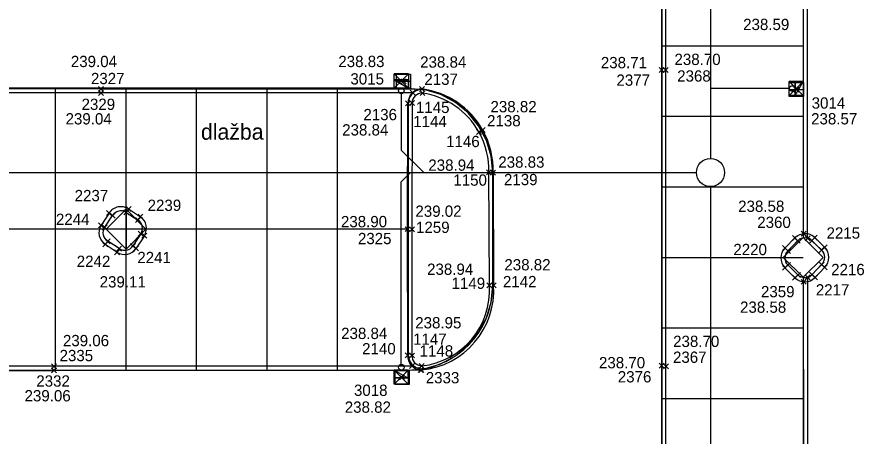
# Model space of a CAD drawing. Extents: x -264222 to -263676, y -1242344 to -1242060.
# Drawn here: x -264148.43 to -264118.41, y -1242246.81 to -1242231.96 of the extents above; entities that cross this region are included whole.
import ezdxf

# ---------------------------------------------------------------- set-up
doc = ezdxf.new("R2010")
doc.units = 0
for name, color, linetype in [('BODY_CISLO', 7, 'Continuous'), ('BODY_SYMBOL', 7, 'Continuous'), ('BODY_VYSKA', 7, 'Continuous'), ('BODY_VYSKY_UV', 7, 'Continuous'), ('KOORDINACNA_SITUACIA_DSP', 7, 'Continuous'), ('POPIS', 7, 'Continuous'), ('PROJEKT_DRS_OBRUBNIKY_KOMUNIKACIE', 7, 'Continuous'), ('PROJEKT_DRS_TDZ_VODOROVNE', 7, 'Continuous'), ('PROJEKT_DRS_UV_STAVBY', 7, 'Continuous'), ('SO_20-3_OBRUBNIKY_DOLNA_HRANA', 7, 'Continuous'), ('SO_20-3_OBRUBNIKY_HORNA_HRANA', 7, 'Continuous'), ('ULICNA_VPUST_POKLOP', 7, 'Continuous')]:
    doc.layers.add(name, color=color, linetype=linetype)

msp = doc.modelspace()

# ---------------------------------------------------------------- linework, layer by layer
at = {"layer": 'BODY_SYMBOL'}
for p, q in [((-264125.67, -1242233.932), (-264125.494, -1242233.756)), ((-264125.494, -1242233.932), (-264125.67, -1242233.756)), ((-264125.527, -1242233.933), (-264125.351, -1242233.757)), ((-264125.351, -1242233.933), (-264125.527, -1242233.757)), ((-264134.821, -1242234.328), (-264134.645, -1242234.152)), ((-264134.645, -1242234.328), (-264134.821, -1242234.152)), ((-264145.543, -1242234.743), (-264145.367, -1242234.567)), ((-264145.367, -1242234.743), (-264145.543, -1242234.567)), ((-264145.541, -1242234.6), (-264145.365, -1242234.424)), ((-264145.365, -1242234.6), (-264145.541, -1242234.424)), ((-264134.502, -1242234.739), (-264134.326, -1242234.563)), ((-264134.326, -1242234.739), (-264134.502, -1242234.563)), ((-264134.167, -1242234.605), (-264133.991, -1242234.429)), ((-264133.991, -1242234.605), (-264134.167, -1242234.429)), ((-264120.898, -1242234.625), (-264120.722, -1242234.449)), ((-264120.722, -1242234.625), (-264120.898, -1242234.449)), ((-264134.149, -1242234.752), (-264133.973, -1242234.576)), ((-264133.973, -1242234.752), (-264134.149, -1242234.576)), ((-264134.664, -1242235.109), (-264134.488, -1242234.933)), ((-264134.488, -1242235.109), (-264134.664, -1242234.933)), ((-264134.517, -1242235.105), (-264134.341, -1242234.929)), ((-264134.341, -1242235.105), (-264134.517, -1242234.929)), ((-264132.148, -1242236.128), (-264131.972, -1242235.952)), ((-264131.972, -1242236.128), (-264132.148, -1242235.952)), ((-264132.017, -1242236.054), (-264131.841, -1242235.878)), ((-264131.841, -1242236.054), (-264132.017, -1242235.878)), ((-264131.797, -1242237.561), (-264131.621, -1242237.385)), ((-264131.621, -1242237.561), (-264131.797, -1242237.385)), ((-264131.649, -1242237.572), (-264131.473, -1242237.396)), ((-264131.473, -1242237.572), (-264131.649, -1242237.396)), ((-264144.565, -1242238.856), (-264144.389, -1242238.68)), ((-264144.389, -1242238.856), (-264144.565, -1242238.68)), ((-264145.254, -1242239), (-264145.078, -1242238.824)), ((-264145.078, -1242239), (-264145.254, -1242238.824)), ((-264145.133, -1242239.089), (-264144.957, -1242238.913)), ((-264144.957, -1242239.089), (-264145.133, -1242238.913)), ((-264144.646, -1242238.975), (-264144.47, -1242238.799)), ((-264144.47, -1242238.975), (-264144.646, -1242238.799)), ((-264144.226, -1242239.248), (-264144.05, -1242239.072)), ((-264144.05, -1242239.248), (-264144.226, -1242239.072)), ((-264144.142, -1242239.129), (-264143.966, -1242238.953)), ((-264143.966, -1242239.129), (-264144.142, -1242238.953)), ((-264145.539, -1242239.434), (-264145.363, -1242239.258)), ((-264145.363, -1242239.434), (-264145.539, -1242239.258)), ((-264145.407, -1242239.506), (-264145.231, -1242239.33)), ((-264145.231, -1242239.506), (-264145.407, -1242239.33)), ((-264144.133, -1242239.733), (-264143.957, -1242239.557)), ((-264143.957, -1242239.733), (-264144.133, -1242239.557)), ((-264144.003, -1242239.802), (-264143.827, -1242239.626)), ((-264143.827, -1242239.802), (-264144.003, -1242239.626)), ((-264134.675, -1242239.571), (-264134.499, -1242239.395)), ((-264134.499, -1242239.571), (-264134.675, -1242239.395)), ((-264134.525, -1242239.573), (-264134.349, -1242239.397)), ((-264134.349, -1242239.573), (-264134.525, -1242239.397)), ((-264120.642, -1242239.734), (-264120.466, -1242239.558)), ((-264120.466, -1242239.734), (-264120.642, -1242239.558)), ((-264145.393, -1242240.113), (-264145.217, -1242239.937)), ((-264145.217, -1242240.113), (-264145.393, -1242239.937)), ((-264145.3, -1242239.997), (-264145.124, -1242239.821)), ((-264145.124, -1242239.997), (-264145.3, -1242239.821)), ((-264120.952, -1242239.881), (-264120.776, -1242239.705)), ((-264120.776, -1242239.881), (-264120.952, -1242239.705)), ((-264120.85, -1242239.985), (-264120.674, -1242239.809)), ((-264120.674, -1242239.985), (-264120.85, -1242239.809)), ((-264120.502, -1242239.891), (-264120.326, -1242239.715)), ((-264120.326, -1242239.891), (-264120.502, -1242239.715)), ((-264120.351, -1242239.976), (-264120.175, -1242239.8)), ((-264120.175, -1242239.976), (-264120.351, -1242239.8)), ((-264120.248, -1242239.871), (-264120.072, -1242239.695)), ((-264120.072, -1242239.871), (-264120.248, -1242239.695)), ((-264144.97, -1242240.393), (-264144.794, -1242240.217)), ((-264144.794, -1242240.393), (-264144.97, -1242240.217)), ((-264144.901, -1242240.259), (-264144.725, -1242240.083)), ((-264144.725, -1242240.259), (-264144.901, -1242240.083)), ((-264144.409, -1242240.165), (-264144.233, -1242239.989)), ((-264144.233, -1242240.165), (-264144.409, -1242239.989)), ((-264144.297, -1242240.248), (-264144.121, -1242240.072)), ((-264144.121, -1242240.248), (-264144.297, -1242240.072)), ((-264121.301, -1242240.234), (-264121.125, -1242240.058)), ((-264121.125, -1242240.234), (-264121.301, -1242240.058)), ((-264121.198, -1242240.342), (-264121.022, -1242240.166)), ((-264121.022, -1242240.342), (-264121.198, -1242240.166)), ((-264120.008, -1242240.31), (-264119.832, -1242240.134)), ((-264119.832, -1242240.31), (-264120.008, -1242240.134)), ((-264119.898, -1242240.211), (-264119.722, -1242240.035)), ((-264119.722, -1242240.211), (-264119.898, -1242240.035)), ((-264121.307, -1242240.941), (-264121.131, -1242240.765)), ((-264121.131, -1242240.941), (-264121.307, -1242240.765)), ((-264121.2, -1242240.84), (-264121.024, -1242240.664)), ((-264121.024, -1242240.84), (-264121.2, -1242240.664)), ((-264120.004, -1242240.824), (-264119.828, -1242240.648)), ((-264119.828, -1242240.824), (-264120.004, -1242240.648)), ((-264119.897, -1242240.928), (-264119.721, -1242240.752)), ((-264119.721, -1242240.928), (-264119.897, -1242240.752)), ((-264120.951, -1242241.292), (-264120.775, -1242241.116)), ((-264120.775, -1242241.292), (-264120.951, -1242241.116)), ((-264120.842, -1242241.192), (-264120.666, -1242241.016)), ((-264120.666, -1242241.192), (-264120.842, -1242241.016)), ((-264120.498, -1242241.273), (-264120.322, -1242241.097)), ((-264120.322, -1242241.273), (-264120.498, -1242241.097)), ((-264120.342, -1242241.178), (-264120.166, -1242241.002)), ((-264120.166, -1242241.178), (-264120.342, -1242241.002)), ((-264120.236, -1242241.281), (-264120.06, -1242241.105)), ((-264120.06, -1242241.281), (-264120.236, -1242241.105)), ((-264131.776, -1242241.562), (-264131.6, -1242241.386)), ((-264131.6, -1242241.562), (-264131.776, -1242241.386)), ((-264131.628, -1242241.56), (-264131.452, -1242241.384)), ((-264131.452, -1242241.56), (-264131.628, -1242241.384)), ((-264120.642, -1242241.437), (-264120.466, -1242241.261)), ((-264120.466, -1242241.437), (-264120.642, -1242241.261)), ((-264134.671, -1242244.046), (-264134.495, -1242243.87)), ((-264134.495, -1242244.046), (-264134.671, -1242243.87)), ((-264134.524, -1242244.047), (-264134.348, -1242243.871)), ((-264134.348, -1242244.047), (-264134.524, -1242243.871)), ((-264147.208, -1242244.427), (-264147.032, -1242244.251)), ((-264147.032, -1242244.427), (-264147.208, -1242244.251)), ((-264147.206, -1242244.576), (-264147.03, -1242244.4)), ((-264147.03, -1242244.576), (-264147.206, -1242244.4)), ((-264134.52, -1242244.421), (-264134.344, -1242244.245)), ((-264134.344, -1242244.421), (-264134.52, -1242244.245)), ((-264134.216, -1242244.557), (-264134.04, -1242244.381)), ((-264134.04, -1242244.557), (-264134.216, -1242244.381)), ((-264134.19, -1242244.559), (-264134.014, -1242244.383)), ((-264134.014, -1242244.559), (-264134.19, -1242244.383)), ((-264134.177, -1242244.414), (-264134.001, -1242244.238)), ((-264134.001, -1242244.414), (-264134.177, -1242244.238)), ((-264125.669, -1242244.412), (-264125.493, -1242244.236)), ((-264125.493, -1242244.412), (-264125.669, -1242244.236)), ((-264125.523, -1242244.428), (-264125.347, -1242244.252)), ((-264125.347, -1242244.428), (-264125.523, -1242244.252)), ((-264134.87, -1242244.827), (-264134.694, -1242244.651)), ((-264134.694, -1242244.827), (-264134.87, -1242244.651))]:
    msp.add_line(p, q, dxfattribs=at)
at = {"layer": 'KOORDINACNA_SITUACIA_DSP'}
for p, q in [((-264123.854, -1242207), (-264123.854, -1242236.976)), ((-264120.568, -1242231.189), (-264120.568, -1242239.774)), ((-264135.061, -1242234.192), (-264134.561, -1242234.192)), ((-264135.061, -1242234.482), (-264135.061, -1242234.192)), ((-264135.061, -1242234.192), (-264134.561, -1242234.482)), ((-264135.061, -1242234.192), (-264134.561, -1242234.482)), ((-264134.561, -1242234.192), (-264135.061, -1242234.192)), ((-264134.561, -1242234.192), (-264134.561, -1242234.482)), ((-264134.561, -1242234.482), (-264134.561, -1242234.192)), ((-264120.858, -1242234.749), (-264120.858, -1242234.249)), ((-264120.858, -1242234.249), (-264120.568, -1242234.249)), ((-264120.858, -1242234.749), (-264120.568, -1242234.249)), ((-264120.858, -1242234.749), (-264120.568, -1242234.249)), ((-264120.568, -1242234.249), (-264120.858, -1242234.249)), ((-264120.858, -1242234.249), (-264120.858, -1242234.749)), ((-264120.568, -1242234.249), (-264120.568, -1242234.749)), ((-264134.561, -1242234.482), (-264135.061, -1242234.482)), ((-264121.058, -1242234.499), (-264123.854, -1242234.499)), ((-264134.811, -1242234.682), (-264134.811, -1242236.68)), ((-264120.568, -1242234.749), (-264120.858, -1242234.749)), ((-264134.568, -1242235.033), (-264134.568, -1242243.932)), ((-264134.811, -1242236.68), (-264134.016, -1242237.476)), ((-264154.318, -1242237.476), (-264124.354, -1242237.476)), ((-264134.811, -1242237.801), (-264134.486, -1242237.476)), ((-264131.568, -1242241.482), (-264131.568, -1242237.482)), ((-264134.811, -1242244.276), (-264134.811, -1242237.801)), ((-264123.854, -1242237.976), (-264123.854, -1242297.736)), ((-264120.568, -1242241.189), (-264120.568, -1242249.774)), ((-264135.068, -1242244.476), (-264134.568, -1242244.476)), ((-264135.068, -1242244.766), (-264135.068, -1242244.476)), ((-264135.068, -1242244.476), (-264134.568, -1242244.766)), ((-264135.068, -1242244.476), (-264134.568, -1242244.766)), ((-264134.568, -1242244.476), (-264135.068, -1242244.476)), ((-264134.568, -1242244.476), (-264134.568, -1242244.766)), ((-264134.568, -1242244.766), (-264134.568, -1242244.476)), ((-264134.568, -1242244.766), (-264135.068, -1242244.766))]:
    msp.add_line(p, q, dxfattribs=at)
for points in [[(-264143.861, -1242239.482), (-264144.568, -1242238.775), (-264145.275, -1242239.482), (-264144.568, -1242240.189)], [(-264120.568, -1242239.775), (-264119.861, -1242240.482), (-264120.568, -1242241.189), (-264121.275, -1242240.482)]]:
    msp.add_lwpolyline(points, close=True, dxfattribs=at)
for centre, radius in [((-264134.811, -1242234.582), 0.1), ((-264120.958, -1242234.499), 0.1), ((-264123.854, -1242237.476), 0.5), ((-264134.811, -1242244.376), 0.1)]:
    msp.add_circle(centre, radius, dxfattribs=at)
for centre, radius, start, end in [((-264134.068, -1242235.033), 0.5, 78.463, 180), ((-264134.568, -1242237.482), 3, 0, 78.463), ((-264134.568, -1242241.482), 3, 281.537, 0), ((-264134.068, -1242243.932), 0.5, 180, 281.537)]:
    msp.add_arc(centre, radius, start, end, dxfattribs=at)
at = {"layer": 'PROJEKT_DRS_OBRUBNIKY_KOMUNIKACIE'}
for p, q in [((-264125.568, -1242270.982), (-264125.568, -1242191.482)), ((-264120.568, -1242231.189), (-264120.568, -1242239.774)), ((-264134.568, -1242234.482), (-264162.528, -1242234.482)), ((-264134.574, -1242234.482), (-264134.068, -1242234.533)), ((-264134.23, -1242234.56), (-264134.311, -1242234.596)), ((-264134.144, -1242234.539), (-264134.23, -1242234.56)), ((-264134.056, -1242234.533), (-264134.144, -1242234.539)), ((-264133.968, -1242234.543), (-264134.056, -1242234.533)), ((-264133.408, -1242234.716), (-264133.968, -1242234.543)), ((-264134.537, -1242234.859), (-264134.56, -1242234.945)), ((-264134.499, -1242234.779), (-264134.537, -1242234.859)), ((-264134.447, -1242234.707), (-264134.499, -1242234.779)), ((-264134.384, -1242234.645), (-264134.447, -1242234.707)), ((-264134.311, -1242234.596), (-264134.384, -1242234.645)), ((-264132.892, -1242234.994), (-264133.408, -1242234.716)), ((-264134.56, -1242234.945), (-264134.568, -1242235.033)), ((-264134.568, -1242235.033), (-264134.568, -1242239.482)), ((-264132.44, -1242235.367), (-264132.892, -1242234.994)), ((-264132.07, -1242235.821), (-264132.44, -1242235.367)), ((-264131.795, -1242236.338), (-264132.07, -1242235.821)), ((-264131.625, -1242236.899), (-264131.795, -1242236.338)), ((-264131.568, -1242237.482), (-264131.625, -1242236.899)), ((-264131.568, -1242241.482), (-264131.568, -1242237.482)), ((-264144.568, -1242238.775), (-264145.275, -1242239.482)), ((-264143.861, -1242239.482), (-264144.568, -1242238.775)), ((-264144.568, -1242238.775), (-264144.568, -1242240.189)), ((-264144.568, -1242240.189), (-264144.568, -1242238.775)), ((-264145.275, -1242239.482), (-264144.568, -1242240.189)), ((-264144.568, -1242240.189), (-264143.861, -1242239.482)), ((-264134.568, -1242239.482), (-264134.568, -1242243.932)), ((-264120.568, -1242241.189), (-264120.568, -1242249.774)), ((-264131.625, -1242242.065), (-264131.568, -1242241.482)), ((-264131.795, -1242242.626), (-264131.625, -1242242.065)), ((-264132.07, -1242243.144), (-264131.795, -1242242.626)), ((-264132.44, -1242243.598), (-264132.07, -1242243.144)), ((-264132.892, -1242243.971), (-264132.44, -1242243.598)), ((-264134.568, -1242243.932), (-264134.56, -1242244.02)), ((-264134.56, -1242244.02), (-264134.537, -1242244.105)), ((-264134.537, -1242244.105), (-264134.499, -1242244.185)), ((-264133.408, -1242244.249), (-264132.892, -1242243.971)), ((-264134.568, -1242244.482), (-264134.068, -1242244.432)), ((-264134.499, -1242244.185), (-264134.447, -1242244.257)), ((-264134.447, -1242244.257), (-264134.384, -1242244.319)), ((-264134.384, -1242244.319), (-264134.311, -1242244.369)), ((-264134.311, -1242244.369), (-264134.23, -1242244.405)), ((-264134.23, -1242244.405), (-264134.144, -1242244.426)), ((-264134.144, -1242244.426), (-264134.056, -1242244.432)), ((-264134.056, -1242244.432), (-264133.968, -1242244.422)), ((-264133.968, -1242244.422), (-264133.408, -1242244.249)), ((-264159.568, -1242244.482), (-264134.568, -1242244.482))]:
    msp.add_line(p, q, dxfattribs=at)
msp.add_lwpolyline([(-264120.568, -1242239.775), (-264119.861, -1242240.482), (-264120.568, -1242241.189), (-264121.275, -1242240.482), (-264120.568, -1242239.775)], dxfattribs=at)
at = {"layer": 'PROJEKT_DRS_TDZ_VODOROVNE'}
for p, q in [((-264125.568, -1242232.982), (-264120.568, -1242232.982)), ((-264125.568, -1242232.982), (-264120.568, -1242232.982)), ((-264147.068, -1242239.482), (-264147.068, -1242234.482)), ((-264144.568, -1242239.482), (-264144.568, -1242234.482)), ((-264142.068, -1242239.482), (-264142.068, -1242234.482)), ((-264139.568, -1242239.482), (-264139.568, -1242234.482)), ((-264137.068, -1242239.482), (-264137.068, -1242234.482)), ((-264125.568, -1242235.482), (-264120.568, -1242235.482)), ((-264125.568, -1242237.982), (-264120.568, -1242237.982)), ((-264134.568, -1242239.482), (-264160.068, -1242239.482)), ((-264147.068, -1242244.482), (-264147.068, -1242239.482)), ((-264144.568, -1242244.482), (-264144.568, -1242239.482)), ((-264142.068, -1242244.482), (-264142.068, -1242239.482)), ((-264139.568, -1242244.482), (-264139.568, -1242239.482)), ((-264137.068, -1242244.482), (-264137.068, -1242239.482)), ((-264125.568, -1242240.482), (-264120.568, -1242240.482)), ((-264125.568, -1242242.982), (-264120.568, -1242242.982)), ((-264125.568, -1242245.482), (-264120.568, -1242245.482))]:
    msp.add_line(p, q, dxfattribs=at)
at = {"layer": 'PROJEKT_DRS_UV_STAVBY'}
for points in [[(-264135.061, -1242234.482), (-264135.061, -1242233.982), (-264134.561, -1242233.982), (-264134.561, -1242234.482), (-264135.061, -1242234.482), (-264134.561, -1242233.982), (-264135.061, -1242233.982), (-264134.561, -1242234.482)], [(-264121.068, -1242234.749), (-264121.068, -1242234.249), (-264120.568, -1242234.249), (-264120.568, -1242234.749), (-264121.068, -1242234.749), (-264120.568, -1242234.249), (-264121.068, -1242234.249), (-264120.568, -1242234.749)], [(-264135.068, -1242244.976), (-264135.068, -1242244.476), (-264134.568, -1242244.476), (-264134.568, -1242244.976), (-264135.068, -1242244.976), (-264134.568, -1242244.476), (-264135.068, -1242244.476), (-264134.568, -1242244.976)]]:
    msp.add_lwpolyline(points, dxfattribs=at)
at = {"layer": 'SO_20-3_OBRUBNIKY_DOLNA_HRANA'}
for p, q in [((-264120.554, -1242239.646), (-264120.56, -1242231.327)), ((-264131.561, -1242237.484), (-264131.54, -1242241.472)), ((-264144.477, -1242238.768), (-264144.054, -1242239.041)), ((-264145.166, -1242238.912), (-264145.451, -1242239.346)), ((-264143.915, -1242239.714), (-264144.209, -1242240.16)), ((-264121.213, -1242240.146), (-264120.864, -1242239.793)), ((-264120.16, -1242239.783), (-264119.81, -1242240.123)), ((-264144.882, -1242240.305), (-264145.305, -1242240.025)), ((-264120.863, -1242241.204), (-264121.219, -1242240.853)), ((-264119.809, -1242240.84), (-264120.148, -1242241.193)), ((-264120.55, -1242249.265), (-264120.554, -1242241.349))]:
    msp.add_line(p, q, dxfattribs=at)
for points in [[(-264125.573, -1242270.915), (-264125.578, -1242264.895), (-264125.575, -1242255.299), (-264125.581, -1242244.324), (-264125.582, -1242233.844), (-264125.584, -1242219.84), (-264125.593, -1242209.81), (-264125.59, -1242197.798), (-264125.59, -1242191.484)], [(-264125.429, -1242270.662), (-264125.437, -1242264.9), (-264125.431, -1242255.315), (-264125.435, -1242244.34), (-264125.439, -1242233.845), (-264125.44, -1242219.841), (-264125.448, -1242209.814), (-264125.447, -1242197.797), (-264125.435, -1242191.484)], [(-264162.587, -1242234.498), (-264152.459, -1242234.502), (-264145.453, -1242234.512), (-264134.079, -1242234.517)], [(-264134.414, -1242234.651), (-264145.455, -1242234.655), (-264152.462, -1242234.648), (-264162.219, -1242234.64)], [(-264134.583, -1242243.958), (-264134.587, -1242239.483), (-264134.576, -1242235.021)], [(-264160.039, -1242244.49), (-264147.118, -1242244.488), (-264134.128, -1242244.469)], [(-264134.432, -1242244.333), (-264147.12, -1242244.339), (-264159.694, -1242244.332)]]:
    msp.add_lwpolyline(points, dxfattribs=at)
for centre, major_axis, ratio, start_param, end_param in [((-264134.072, -1242235.021), (-0.397, 0.312), 0.999984, 5.393344, 6.948544), ((-264134.455, -1242237.395), (-2.194, 1.904), 0.999013, 4.371651, 5.296899), ((-264134.436, -1242237.377), (-0.333, 2.858), 0.999986, 4.559286, 5.109056), ((-264144.75, -1242239.183), (-0.302, -0.395), 0.999396, 3.212064, 4.786495), ((-264144.346, -1242239.452), (-0.355, 0.357), 0.999968, 3.383514, 4.883804), ((-264145.029, -1242239.611), (0.039, -0.496), 0.999764, 4.073201, 5.617222), ((-264120.507, -1242240.147), (-0.499, -0.063), 0.999917, 3.825435, 5.37776), ((-264144.62, -1242239.884), (0.087, 0.488), 0.999601, 2.761666, 4.298008), ((-264120.861, -1242240.502), (-0.137, -0.482), 0.999773, 4.197765, 5.764757), ((-264120.165, -1242240.482), (-0.208, 0.46), 0.999856, 3.500163, 5.07907), ((-264134.361, -1242241.656), (2.549, -1.221), 0.999993, 5.25084, 6.795201), ((-264120.511, -1242240.856), (0.479, 0.128), 0.998676, 3.659329, 5.271157), ((-264134.089, -1242243.977), (-0.338, 0.36), 0.999977, 0.778868, 2.362725)]:
    msp.add_ellipse(centre, major_axis=major_axis, ratio=ratio, start_param=start_param, end_param=end_param, dxfattribs=at)
at = {"layer": 'SO_20-3_OBRUBNIKY_HORNA_HRANA'}
for p, q in [((-264120.414, -1242239.803), (-264120.418, -1242231.165)), ((-264131.688, -1242241.474), (-264131.709, -1242237.473)), ((-264145.319, -1242239.418), (-264145.045, -1242239.001)), ((-264144.558, -1242238.887), (-264144.138, -1242239.16)), ((-264144.045, -1242239.645), (-264144.321, -1242240.077)), ((-264144.813, -1242240.171), (-264145.212, -1242239.909)), ((-264121.11, -1242240.254), (-264120.762, -1242239.897)), ((-264120.263, -1242239.888), (-264119.92, -1242240.222)), ((-264120.754, -1242241.104), (-264121.112, -1242240.752)), ((-264119.916, -1242240.736), (-264120.254, -1242241.09)), ((-264120.405, -1242249.415), (-264120.41, -1242241.185))]:
    msp.add_line(p, q, dxfattribs=at)
msp.add_lwpolyline([(-264134.429, -1242235.017), (-264134.437, -1242239.485), (-264134.436, -1242243.959)], dxfattribs=at)
for centre, major_axis, ratio, start_param, end_param in [((-264134.072, -1242235.021), (-0.2, -0.296), 0.999825, 3.705819, 5.296628), ((-264134.454, -1242237.38), (-2.056, 1.821), 0.998551, 4.377204, 5.293031), ((-264134.535, -1242237.406), (0.826, 2.704), 0.999992, 4.984988, 5.51296), ((-264144.745, -1242239.189), (-0.315, -0.164), 0.995314, 3.68017, 5.243265), ((-264144.341, -1242239.45), (-0.111, 0.337), 0.999878, 3.811531, 5.352745), ((-264145.049, -1242239.617), (0.112, -0.317), 0.995552, 3.740013, 5.43064), ((-264120.508, -1242240.148), (-0.35, -0.068), 0.999401, 3.763697, 5.311979), ((-264144.615, -1242239.873), (-0.038, 0.356), 0.999711, 2.44722, 3.998626), ((-264120.863, -1242240.504), (-0.022, -0.351), 0.999429, 3.985395, 5.558342), ((-264120.15, -1242240.481), (0.058, 0.342), 0.999012, 4.052736, 5.724046), ((-264120.511, -1242240.844), (0.351, 0.059), 0.998294, 3.796516, 5.353487), ((-264134.375, -1242241.649), (2.486, -1.034), 0.999991, 5.212651, 6.742239), ((-264134.077, -1242243.967), (0.132, -0.334), 0.999943, 4.312248, 5.872985)]:
    msp.add_ellipse(centre, major_axis=major_axis, ratio=ratio, start_param=start_param, end_param=end_param, dxfattribs=at)
at = {"layer": 'ULICNA_VPUST_POKLOP'}
for p, q in [((-264134.733, -1242234.24), (-264134.733, -1242234.24)), ((-264120.81, -1242234.537), (-264120.81, -1242234.537)), ((-264134.782, -1242244.739), (-264134.782, -1242244.739))]:
    msp.add_line(p, q, dxfattribs=at)
for points in [[(-264134.983, -1242234.24), (-264134.983, -1242233.99), (-264134.483, -1242233.99), (-264134.483, -1242234.49), (-264134.983, -1242234.49), (-264134.983, -1242234.24), (-264134.483, -1242234.24)], [(-264121.06, -1242234.537), (-264121.06, -1242234.287), (-264120.56, -1242234.287), (-264120.56, -1242234.787), (-264121.06, -1242234.787), (-264121.06, -1242234.537), (-264120.56, -1242234.537)], [(-264135.032, -1242244.739), (-264135.032, -1242244.489), (-264134.532, -1242244.489), (-264134.532, -1242244.989), (-264135.032, -1242244.989), (-264135.032, -1242244.739), (-264134.532, -1242244.739)]]:
    msp.add_lwpolyline(points, dxfattribs=at)

# ---------------------------------------------------------------- texts
at = {"layer": 'BODY_CISLO'}
for s, p in [('2327', (-264145.811, -1242234.345)), ('3015', (-264136.616, -1242234.358)), ('2137', (-264133.995, -1242234.371)), ('2368', (-264125.035, -1242234.255)), ('2377', (-264127.187, -1242234.402)), ('2329', (-264146.144, -1242235.259)), ('3014', (-264120.269, -1242235.213)), ('1145', (-264134.293, -1242235.368)), ('2136', (-264136.155, -1242235.623)), ('1144', (-264134.388, -1242235.868)), ('2138', (-264131.772, -1242235.841)), ('1146', (-264133.224, -1242236.576)), ('1150', (-264132.967, -1242237.943)), ('2139', (-264131.173, -1242237.925)), ('2237', (-264146.388, -1242238.493)), ('2239', (-264143.802, -1242238.837)), ('2244', (-264147.052, -1242239.333)), ('2360', (-264122.197, -1242239.44)), ('1259', (-264134.29, -1242239.617)), ('2325', (-264136.349, -1242240.015)), ('2215', (-264119.742, -1242239.819)), ('2220', (-264123.044, -1242240.403)), ('2242', (-264146.314, -1242240.822)), ('2241', (-264144.167, -1242240.687)), ('2216', (-264119.578, -1242241.113)), ('2142', (-264131.21, -1242241.541)), ('1149', (-264133.031, -1242241.599)), ('2217', (-264120.122, -1242241.833)), ('2359', (-264122.065, -1242241.896)), ('1147', (-264134.394, -1242243.58)), ('2140', (-264136.201, -1242243.919)), ('2335', (-264146.923, -1242244.161)), ('1148', (-264134.162, -1242243.996)), ('2367', (-264125.183, -1242244.22)), ('2332', (-264147.747, -1242245.063)), ('2333', (-264133.945, -1242244.945)), ('2376', (-264127.139, -1242244.913)), ('3018', (-264136.49, -1242245.391))]:
    msp.add_text(s, height=0.4, dxfattribs=at).set_placement(p)
at = {"layer": 'BODY_VYSKA'}
for s, p in [('238.59', (-264122.697, -1242232.429)), ('239.04', (-264146.523, -1242233.741)), ('238.84', (-264134.143, -1242233.761)), ('238.70', (-264125.131, -1242233.667)), ('238.71', (-264127.74, -1242233.781)), ('238.82', (-264131.652, -1242235.342)), ('239.04', (-264146.711, -1242235.773)), ('238.84', (-264136.907, -1242236.165)), ('238.83', (-264131.374, -1242237.306)), ('238.94', (-264133.853, -1242237.414)), ('238.58', (-264122.874, -1242238.871)), ('239.02', (-264134.312, -1242239.046)), ('238.90', (-264136.951, -1242239.415)), ('238.82', (-264131.158, -1242240.944)), ('238.94', (-264133.898, -1242241.102)), ('239.11', (-264145.502, -1242241.549)), ('238.58', (-264122.806, -1242242.446)), ('238.95', (-264134.318, -1242242.999)), ('238.84', (-264136.944, -1242243.376)), ('239.06', (-264146.804, -1242243.631)), ('238.70', (-264125.179, -1242243.658)), ('238.70', (-264127.806, -1242244.413)), ('239.06', (-264148.164, -1242245.585))]:
    msp.add_text(s, height=0.4, dxfattribs=at).set_placement(p)
at = {"layer": 'BODY_VYSKY_UV'}
for s, p in [('238.83', (-264137.043, -1242233.741)), ('238.57', (-264120.288, -1242235.772)), ('238.82', (-264136.815, -1242245.988))]:
    msp.add_text(s, height=0.4, dxfattribs=at).set_placement(p)
at = {"layer": 'POPIS'}
msp.add_text('dlažba', height=0.5625, rotation=360, dxfattribs=at).set_placement((-264141.911, -1242236.313))

doc.saveas('drawing.dxf')
